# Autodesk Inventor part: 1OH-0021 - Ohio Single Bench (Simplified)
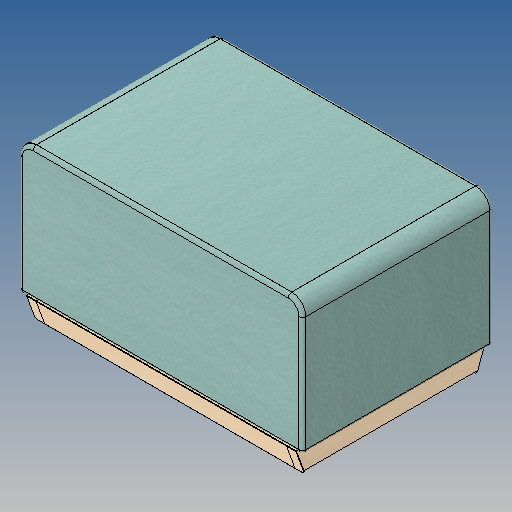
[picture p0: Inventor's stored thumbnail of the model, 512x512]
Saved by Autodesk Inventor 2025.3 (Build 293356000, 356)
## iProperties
Created: 2025-11
Part Number: 1OH-0021 - Ohio Single Bench (Simplified)
Material: Generic
Document SubType Name: Modeling
Designer: craig.ferris
Density: 1 g/cm^3
Appearance: CADET-ZEST SEAFOAM (219)
Author: craig.ferris
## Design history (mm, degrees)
derived "1OH-0021 - OHIO BENCH - SINGLE (Rev B) - Enclosed Plinth - U"
body "Solid1"
body "Solid2"
body "Solid3"
body "Solid4"
body "Solid5"
body "Solid6"
body "Solid7"
body "Solid8"
body "Solid9"
body "Solid10"
body "Solid11"
body "Solid12"
body "Solid13"
body "Solid14"
